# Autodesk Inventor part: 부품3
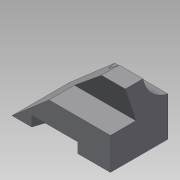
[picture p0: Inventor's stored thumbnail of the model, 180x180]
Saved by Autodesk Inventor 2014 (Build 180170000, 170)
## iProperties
Created: 2015-04
Part Number: 부품3
Material: Generic
Document SubType Name: Modeling
Designer: 203-02
Density: 1 g/cm^3
Appearance: Default
Author: 203-02
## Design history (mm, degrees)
sketch "스케치1"
  geometry: L1 (-67.5, -39.5)-(67.5, -39.5); L2 (67.5, -39.5)-(67.5, 39.5); L3 (67.5, 39.5)-(-67.5, 39.5); L4 (-67.5, 39.5)-(-67.5, -39.5); L5 (-67.5, -39.5)-(67.5, 39.5); L6 (67.5, -39.5)-(-67.5, 39.5); 1 further point
  constraints: 12 end point, 2 midpoint, 2 parallel, 1 horizontal, 1 perpendicular
  dimensions: "d0" = 135 distance of L3.end L2.end; "d1" = 79 distance of L2.end L1.end
extrude "돌출1" new body sketch "스케치1" distance "d2" = 89; taper "d3" = 0 deg
sketch "스케치2"
  geometry: L1 (0, 0)-(135, 0) reference; L2 (0, 89)-(135, 89) reference; L3 (0, 0)-(0, 89) reference; L4 (0, 0)-(102.383, 89); L5 (0, 0)-(0, 89); L6 (0, 89)-(102.383, 89); 1 further point
  constraints: 6 end point, 1 collinear, 1 perpendicular, 1 point on line
  dimensions: "d4" = 41 deg angle of L1 L4
extrude "돌출2" cut sketch "스케치2" distance "d5" = 89; taper "d6" = 0 deg
sketch "스케치3"
  geometry: L1 (-89, 0)-(-89, 79) reference; L2 (0, 0)-(-89, 0) reference; L3 (0, 0)-(-44, 0); L4 (-44, 0)-(-44, 35); L5 (-44, 35)-(-89, 20.379); L6 (-44, 0)-(-89, 0); L7 (-89, 0)-(-89, 20.379); 1 further point
  constraints: 10 end point, 2 perpendicular, 2 point on line, 1 collinear
  dimensions: "d7" = 44 distance of L2.start L3.end; "d8" = 35 distance of L3.end L4.end; "d9" = 72 deg angle of L4 L5
extrude "돌출3" cut sketch "스케치3" distance "d10" = 89; taper "d11" = 0 deg
sketch "스케치4"
  geometry: L1 (-89, 20.379)-(-89, 79) reference; L2 (0, 79)-(0, 88); L3 (0, 88)-(-97, 88); L4 (-89, 79)-(-97, 79); L5 (-97, 79)-(-97, 88); C1 r 44 at (-97, 88); 1 further point
  constraints: 8 end point, 2 parallel, 2 perpendicular, 1 centre point, 1 coincident
  dimensions: "d12" = 9 distance of L2.start L2.end; "d13" = 8 distance of L1.end L4.end; "d14" = 88 diameter of C1
extrude "돌출4" cut sketch "스케치4" distance "d15" = 89; taper "d16" = 0 deg
sketch "스케치7"
  geometry: L1 (-67.5, 39.5)-(-5.46, 39.5) reference; L2 (-67.5, 39.5)-(-67.5, -39.5) reference; L3 (-5.46, 39.5)-(67.5, 39.5) reference; L4 (67.5, 39.5)-(67.5, 5.233) reference; L5 (67.5, -4.5)-(67.5, -39.5) reference; L6 (-67.5, -39.5)-(-40.5, -39.5); L7 (-40.5, -39.5)-(-14.831, 39.5); L8 (48.256, 39.5)-(22.588, -39.5); L9 (-40.5, -39.5)-(22.588, -39.5); L10 (-14.831, 39.5)-(48.256, 39.5); L11 (-40.5, -39.5)-(22.588, -39.5); L12 (-40.5, -39.5)-(22.588, -39.5); 1 further point
  constraints: 14 end point, 3 collinear, 3 point on line, 2 parallel, 1 perpendicular
  dimensions: "d23" = 27 distance of L2.end L6.end; "d24" = 72 deg angle of L8 L3; "d25" = 60 distance between parallel lines of L8 L7
extrude "돌출6" cut sketch "스케치7" distance "d26" = 14; taper "d27" = 0 deg
node "솔리드1"
